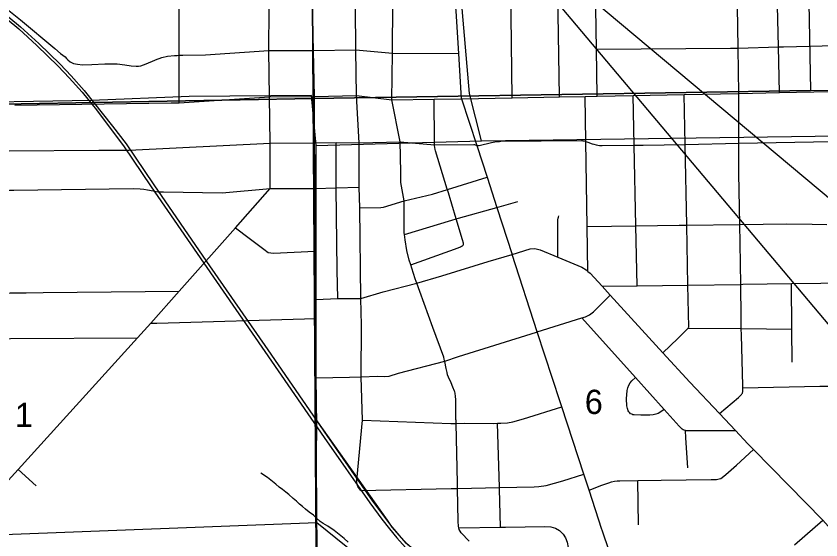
# Model space of a CAD drawing. Extents: x 0 to 34, y 0 to 22.
# Drawn here: x 5.027 to 6.418, y 16.498 to 17.402 of the extents above; entities that cross this region are included whole.
import ezdxf

# ---------------------------------------------------------------- set-up
doc = ezdxf.new("R2010")
doc.units = 0
for name, color, linetype in [('GM_X_City_Street', 7, 'Continuous'), ('GM_X_Corporation', 7, 'Continuous'), ('GM_X_County_Road', 7, 'Continuous'), ('GM_X_Minor_River', 7, 'Continuous'), ('GM_X_Rail_Line', 7, 'Continuous'), ('GM_X_Section', 7, 'Continuous'), ('GM_X_Section_Text', 7, 'Continuous'), ('GM_X_State_Route', 7, 'Continuous'), ('SH_Text', 7, 'Continuous')]:
    doc.layers.add(name, color=color, linetype=linetype)

msp = doc.modelspace()

# ---------------------------------------------------------------- linework, layer by layer
at = {"layer": 'GM_X_City_Street'}
for p, q in [((6.1837, 16.6865), (6.2703, 16.6865)), ((5.03, 16.6191), (5.0615, 16.5908)), ((6.1024, 16.5238), (6.1014, 16.6003))]:
    msp.add_line(p, q, dxfattribs=at)
for points in [[(4.1481, 17.9446), (4.2247, 17.9013), (4.4561, 17.768), (4.7359, 17.6069), (4.8227, 17.5546), (4.8729, 17.5196), (4.9113, 17.4921), (4.9734, 17.4451), (5.0344, 17.3959), (5.0935, 17.3462), (5.1031, 17.338), (5.1112, 17.3317), (5.1139, 17.329), (5.1162, 17.3268)], [(5.4635, 17.3427), (5.4638, 17.4154), (5.4533, 17.4767), (5.4528, 17.5426), (5.4528, 17.5447), (5.4522, 17.6127), (5.4525, 17.6801), (5.4525, 17.6808), (5.4527, 17.749), (5.4527, 17.75), (5.453, 17.829)], [(5.8843, 17.2611), (5.8824, 17.4022), (5.8823, 17.4136), (5.8823, 17.4168), (5.8817, 17.4843), (5.8813, 17.5375), (5.8813, 17.5391), (5.8814, 17.5404), (5.8817, 17.5417), (5.882, 17.5428), (5.8834, 17.5477), (5.8839, 17.5493), (5.8842, 17.5505), (5.8844, 17.5516), (5.8845, 17.5528), (5.8844, 17.5573), (5.8839, 17.6149), (5.8835, 17.6496)], [(6.031, 17.264), (6.0297, 17.3452), (6.0286, 17.416), (6.0286, 17.4204), (6.0275, 17.4867), (6.0266, 17.5475), (6.0265, 17.5507), (6.0255, 17.616)], [(5.9658, 17.2627), (5.9636, 17.4064), (5.9635, 17.4149), (5.9625, 17.4857), (5.9615, 17.5501)], [(5.6139, 17.3439), (5.6132, 17.4171), (5.6124, 17.4855)], [(5.677, 17.3382), (5.6772, 17.3549), (5.6778, 17.4096), (5.6787, 17.481)], [(6.3464, 17.2701), (6.3446, 17.3491), (6.343, 17.4203), (6.343, 17.4229), (6.3428, 17.4295)], [(6.0297, 17.3452), (6.2615, 17.3468), (6.2747, 17.3471), (6.3446, 17.3491), (6.3533, 17.3493), (6.4424, 17.3518), (6.5072, 17.3531), (6.5172, 17.3533), (6.5466, 17.3531), (6.5887, 17.3529), (6.757, 17.352)], [(5.1162, 17.3268), (5.12, 17.3234), (5.1226, 17.322), (5.1256, 17.3207), (5.1294, 17.3197), (5.1329, 17.3191), (5.1414, 17.3184), (5.1573, 17.3187), (5.1801, 17.3198), (5.1922, 17.32), (5.1971, 17.32), (5.1994, 17.3199), (5.2013, 17.3197), (5.2146, 17.318), (5.2257, 17.3163), (5.234, 17.3156), (5.2381, 17.3158), (5.242, 17.3165), (5.247, 17.318), (5.2514, 17.3197), (5.2665, 17.3264), (5.2674, 17.3267), (5.2786, 17.3307), (5.2884, 17.3332), (5.3003, 17.3344), (5.3051, 17.3345), (5.3085, 17.3346), (5.3146, 17.3347), (5.3541, 17.3353), (5.4635, 17.3427)], [(6.1446, 16.8207), (6.1705, 16.8454), (6.1862, 16.8612), (6.1886, 16.8636), (6.1892, 16.8643), (6.1896, 16.865), (6.1881, 16.9377), (6.186, 17.0415), (6.1832, 17.1808), (6.1814, 17.2669)], [(5.8, 17.008), (5.8001, 17.0094), (5.8001, 17.0101), (5.7984, 17.016), (5.7874, 17.052), (5.7721, 17.1026), (5.7718, 17.1033), (5.7517, 17.1698), (5.7511, 17.1717), (5.7503, 17.1756), (5.75, 17.1787), (5.7499, 17.18), (5.7498, 17.1857), (5.7491, 17.2588)], [(6.0151, 16.9614), (6.0139, 17.039), (6.0115, 17.1859), (6.0103, 17.2636)], [(6.1002, 16.9365), (6.098, 17.0402), (6.0949, 17.1793), (6.0931, 17.2652)], [(5.583, 16.9143), (5.5814, 16.9637), (5.5799, 17.1056), (5.5799, 17.1839)], [(5.6226, 16.5831), (5.6187, 16.5879), (5.6175, 16.5898), (5.6167, 16.5916), (5.6161, 16.5939), (5.6158, 16.5958), (5.6155, 16.6), (5.6255, 16.7047), (5.623, 16.7795), (5.6235, 16.8684), (5.6227, 16.9143), (5.6207, 17.0714), (5.6197, 17.1071), (5.6194, 17.1836)], [(5.81, 16.4955), (5.7962, 16.5101), (5.7941, 16.513), (5.7927, 16.5156), (5.7917, 16.5184), (5.7912, 16.5209), (5.7906, 16.5298), (5.7898, 16.5867), (5.7898, 16.5887), (5.7897, 16.5954), (5.7872, 16.6988), (5.7871, 16.7042), (5.787, 16.7052), (5.7866, 16.7382), (5.7861, 16.7473), (5.7859, 16.7495), (5.7856, 16.7513), (5.7852, 16.7531), (5.7847, 16.7546), (5.7817, 16.7617), (5.7786, 16.7688), (5.7739, 16.779), (5.7725, 16.783), (5.7715, 16.7866), (5.7703, 16.7938), (5.7678, 16.8055), (5.7676, 16.8065), (5.7674, 16.8073), (5.7668, 16.81), (5.7658, 16.8134), (5.7469, 16.8644), (5.7245, 16.9267), (5.7194, 16.9409), (5.7182, 16.9441), (5.7166, 16.9487), (5.7106, 16.9672), (5.7088, 16.973), (5.7063, 16.9808), (5.7023, 16.9974), (5.699, 17.016), (5.6978, 17.0251), (5.6974, 17.0278), (5.6975, 17.0833), (5.6914, 17.1152), (5.6917, 17.1309), (5.6911, 17.1603), (5.6906, 17.1854)], [(5.6207, 17.0714), (5.6572, 17.0719), (5.6615, 17.0726), (5.6975, 17.0833), (5.7465, 17.0945), (5.7721, 17.1026), (5.8407, 17.124)], [(4.7895, 17.1005), (4.8605, 17.1009), (4.8969, 17.101), (4.9452, 17.1013), (5.015, 17.1017), (5.0228, 17.1017), (5.2292, 17.1044), (5.2413, 17.1041), (5.2473, 17.1036), (5.2535, 17.1025), (5.2638, 17.1004), (5.2689, 17.0992), (5.2722, 17.0988), (5.2813, 17.0986), (5.3826, 17.0972), (5.4656, 17.1045), (5.5437, 17.1048)], [(5.5437, 17.1048), (5.5799, 17.1056), (5.6197, 17.1071)], [(5.6978, 17.0251), (5.7801, 17.0499), (5.7874, 17.052), (5.7913, 17.0531), (5.8577, 17.072), (5.8942, 17.0823)], [(5.9629, 16.9862), (5.9633, 17.0504), (5.9635, 17.0532), (5.964, 17.0553), (5.9651, 17.0572)], [(6.0139, 17.039), (6.098, 17.0402), (6.1728, 17.0414), (6.186, 17.0415), (6.2778, 17.0424), (6.318, 17.0428), (6.3582, 17.0434), (6.4026, 17.0429), (6.428, 17.0422)], [(5.4056, 17.0366), (5.4297, 17.0187), (5.455, 16.9999), (5.4624, 16.9943), (5.4717, 16.9928), (5.5432, 16.9961)], [(5.7088, 16.973), (5.7906, 17.0022), (5.7947, 17.0039), (5.7965, 17.0048), (5.7982, 17.0057), (5.7989, 17.0062), (5.7994, 17.0067), (5.8, 17.008)], [(6.0395, 16.9356), (6.1002, 16.9365), (6.1881, 16.9377), (6.2793, 16.939), (6.2831, 16.9391), (6.3668, 16.9403), (6.4176, 16.941), (6.4415, 16.9414), (6.5008, 16.9424), (6.5679, 16.9435), (6.6341, 16.9446), (6.6397, 16.9447), (6.7024, 16.9457), (6.7059, 16.9458), (6.7144, 16.9459)], [(6.3679, 16.8047), (6.3675, 16.8616), (6.3668, 16.9403)], [(4.7893, 16.9222), (4.9006, 16.9233), (4.9484, 16.9237), (5.0165, 16.9244), (5.0439, 16.9246), (5.0733, 16.9249), (5.3084, 16.9272)], [(5.5455, 16.7774), (5.603, 16.7785), (5.623, 16.7795), (5.6516, 16.7802), (5.6635, 16.78), (5.6714, 16.7805), (5.6876, 16.7856), (5.7676, 16.8065), (5.7916, 16.8142), (5.9262, 16.8566), (5.9276, 16.857), (6.0043, 16.8812), (6.0107, 16.8832), (6.0178, 16.8864), (6.0246, 16.8914), (6.0535, 16.9203)], [(6.1876, 16.6223), (6.1844, 16.674), (6.1837, 16.6865), (6.1817, 16.687), (6.1798, 16.6879), (6.1783, 16.6889), (6.1768, 16.6902), (6.1726, 16.6943), (6.1469, 16.7227), (6.0971, 16.7781), (6.0043, 16.8812)], [(6.1886, 16.8636), (6.2803, 16.8626), (6.3675, 16.8616)], [(4.7906, 16.8438), (4.8854, 16.8445), (4.9028, 16.8446), (4.9453, 16.8449), (5.0171, 16.8453), (5.2367, 16.8468)], [(6.1469, 16.7227), (6.1397, 16.7177), (6.1366, 16.7159), (6.1325, 16.7146), (6.1279, 16.7137), (6.1219, 16.7133), (6.1067, 16.713), (6.0949, 16.7136), (6.0929, 16.7139), (6.0909, 16.7146), (6.0889, 16.7156), (6.0873, 16.7169), (6.0859, 16.7188), (6.0848, 16.7206), (6.0834, 16.7245), (6.0826, 16.729), (6.082, 16.7411), (6.083, 16.7556), (6.084, 16.7601), (6.0859, 16.7647), (6.0884, 16.7689), (6.0912, 16.7722), (6.0971, 16.7781)], [(6.2829, 16.7601), (6.4163, 16.7629), (6.4349, 16.7632), (6.447, 16.7626), (6.4675, 16.7618), (6.4865, 16.7613), (6.5013, 16.7611), (6.5054, 16.7612), (6.5164, 16.7614), (6.5707, 16.7623), (6.6393, 16.7636), (6.7072, 16.7648), (6.7836, 16.7662)], [(5.6255, 16.7047), (5.7784, 16.6986), (5.7872, 16.6988), (5.8015, 16.6993), (5.8524, 16.6989), (5.8588, 16.699), (5.8644, 16.699), (5.8759, 16.6997), (5.8853, 16.7013), (5.9035, 16.7065), (5.9699, 16.7272)], [(5.8639, 16.5197), (5.862, 16.5857), (5.862, 16.588), (5.8588, 16.699)], [(6.0172, 16.5835), (6.0389, 16.592), (6.0511, 16.5963), (6.0559, 16.5979), (6.0611, 16.599), (6.0656, 16.5996), (6.07, 16.5999), (6.1014, 16.6003), (6.142, 16.6008), (6.2281, 16.6021), (6.2372, 16.6022), (6.2398, 16.6025), (6.2422, 16.603), (6.2447, 16.6039), (6.247, 16.6054), (6.2534, 16.6104), (6.2721, 16.627), (6.3014, 16.6537)], [(5.6226, 16.5831), (5.7788, 16.5865), (5.7898, 16.5867), (5.862, 16.588), (5.9221, 16.5891), (5.9301, 16.5896), (5.943, 16.5917), (5.9717, 16.5997), (6.0081, 16.6112)], [(5.7917, 16.5184), (5.8639, 16.5197), (5.8724, 16.5198), (5.9409, 16.521), (5.9508, 16.5204), (5.9592, 16.5181), (5.966, 16.5138), (5.9722, 16.5078), (5.9765, 16.501), (5.9791, 16.4935), (5.9808, 16.4848), (5.9817, 16.4746), (5.9826, 16.4625)]]:
    msp.add_lwpolyline(points, dxfattribs=at)
at = {"layer": 'GM_X_Corporation'}
msp.add_lwpolyline([(5.6299, 16.46), (5.5464, 16.5271), (4.7945, 16.4985)], dxfattribs=at)
at = {"layer": 'GM_X_County_Road'}
for p, q in [((5.6149, 17.2651), (5.6139, 17.3439)), ((5.6194, 17.1836), (5.6149, 17.2651))]:
    msp.add_line(p, q, dxfattribs=at)
for points in [[(5.5425, 17.2636), (5.5405, 17.3429), (5.5388, 17.4169), (5.5378, 17.4844), (5.5371, 17.5514), (5.5372, 17.6185), (5.5367, 17.6863), (5.5364, 17.7569), (5.5358, 17.8344), (5.5351, 17.9031), (5.5346, 18.0161)], [(5.3087, 17.2528), (5.3085, 17.3346), (5.3084, 17.3966), (5.3084, 17.4042), (5.3083, 17.4734), (5.3083, 17.5427), (5.3083, 17.5764), (5.3082, 17.6037), (5.308, 17.6793), (5.3079, 17.6981), (5.3074, 17.7045), (5.3066, 17.7102), (5.3046, 17.7183), (5.3031, 17.722), (5.3018, 17.7246), (5.2893, 17.7472), (5.2454, 17.8264), (5.2187, 17.8971)], [(6.28, 16.8817), (6.2793, 16.939), (6.2783, 17.0104), (6.2778, 17.0424), (6.2761, 17.1306), (6.2761, 17.1826), (6.2762, 17.2688), (6.2747, 17.3471), (6.2734, 17.4188)], [(5.4635, 17.3427), (5.5405, 17.3429), (5.6139, 17.3439), (5.677, 17.3382), (5.7921, 17.3377)], [(5.4656, 17.1045), (5.4656, 17.1826), (5.4645, 17.263), (5.4635, 17.3427)], [(5.6906, 17.1854), (5.676, 17.2579), (5.677, 17.3382)], [(6.0115, 17.1859), (6.0149, 17.1848), (6.0225, 17.1818), (6.0255, 17.1809), (6.0291, 17.18), (6.0321, 17.1794), (6.035, 17.179), (6.04, 17.1787), (6.0949, 17.1793), (6.1107, 17.1795), (6.1832, 17.1808), (6.2761, 17.1826), (6.4375, 17.1855), (6.4899, 17.1865), (6.4982, 17.1866), (6.5584, 17.188), (6.5663, 17.1881), (6.626, 17.1893), (6.8006, 17.1927), (6.828, 17.1935), (6.8565, 17.1955), (6.9136, 17.2006)], [(5.0067, 17.1695), (5.0144, 17.1695), (5.1695, 17.1705), (5.1907, 17.1709), (5.2221, 17.171), (5.4656, 17.1826), (5.5424, 17.1836)], [(5.5424, 17.1836), (5.5799, 17.1839), (5.6194, 17.1836), (5.6906, 17.1854), (5.7499, 17.18), (5.8177, 17.1808), (5.8192, 17.1805), (5.8203, 17.1802), (5.8228, 17.179), (5.8238, 17.1789), (5.825, 17.1789), (5.8261, 17.179), (5.827, 17.1791), (5.8484, 17.1839), (5.8544, 17.1852), (5.8568, 17.1855), (5.8591, 17.1858), (5.862, 17.186), (5.8646, 17.1861), (6.004, 17.1872), (6.005, 17.1872), (6.0064, 17.1871), (6.0076, 17.187), (6.0089, 17.1867), (6.0101, 17.1863), (6.0115, 17.1859)], [(5.2594, 16.8718), (5.3084, 16.9272), (5.4056, 17.0366), (5.4656, 17.1045)], [(5.6227, 16.9143), (5.6613, 16.9259), (5.7194, 16.9409), (5.7625, 16.9538), (5.8428, 16.9787), (5.8842, 16.9903)], [(6.0398, 16.5147), (6.0394, 16.5157), (6.0172, 16.5835), (6.0081, 16.6112), (5.9699, 16.7272), (5.9669, 16.7364), (5.9276, 16.857), (5.8842, 16.9903)], [(5.5447, 16.913), (5.583, 16.9143), (5.6227, 16.9143)], [(5.5466, 16.5236), (5.5465, 16.5347), (5.5457, 16.6416), (5.5467, 16.6961), (5.5455, 16.7774), (5.5447, 16.8801)], [(6.2427, 16.7159), (6.2752, 16.7437), (6.2805, 16.7488), (6.2814, 16.7499), (6.2821, 16.7511), (6.2825, 16.7521), (6.2827, 16.7531), (6.2829, 16.7554), (6.283, 16.7579), (6.2829, 16.7601), (6.2828, 16.7645), (6.2804, 16.8512), (6.2803, 16.8626), (6.28, 16.8817)], [(6.3722, 16.4893), (6.3902, 16.5044), (6.4212, 16.5319)], [(5.552, 15.8685), (5.5516, 15.9077), (5.5507, 16.0068), (5.5494, 16.1864), (5.5493, 16.3182), (5.5486, 16.379), (5.5477, 16.4263), (5.5467, 16.4698), (5.547, 16.4932), (5.5468, 16.5074), (5.5466, 16.5236)], [(6.1317, 16.258), (6.1173, 16.2956), (6.0982, 16.3453), (6.0941, 16.3559), (6.0617, 16.4482), (6.056, 16.4656), (6.0522, 16.4769), (6.0398, 16.5147)]]:
    msp.add_lwpolyline(points, dxfattribs=at)
at = {"layer": 'GM_X_Minor_River'}
for points in [[(5.5115, 16.5646), (5.5054, 16.5694), (5.498, 16.5761), (5.493, 16.5802), (5.4873, 16.5846), (5.4811, 16.589), (5.4757, 16.5939), (5.4672, 16.6009), (5.4611, 16.6053), (5.4499, 16.6127)], [(5.6005, 16.4939), (5.5939, 16.5002), (5.5851, 16.5069), (5.5766, 16.5139), (5.5655, 16.5213), (5.5574, 16.5257), (5.552, 16.5297), (5.5451, 16.5357), (5.5408, 16.5405), (5.5335, 16.5457), (5.527, 16.5505), (5.5216, 16.5553), (5.5166, 16.5594), (5.5115, 16.5646)]]:
    msp.add_lwpolyline(points, dxfattribs=at)
at = {"layer": 'GM_X_Rail_Line'}
msp.add_line((5.5454, 17.1789), (5.8309, 17.1868), dxfattribs=at)
for points in [[(5.8309, 17.1868), (5.8105, 17.2685), (5.7839, 17.5759), (6.0398, 17.9469)], [(5.0113, 17.3969), (5.0313, 17.3802), (5.0627, 17.3515), (5.0994, 17.316), (5.1183, 17.2959), (5.1409, 17.271), (5.1658, 17.2404), (5.189, 17.209), (5.2125, 17.1783), (5.26, 17.1076), (5.3514, 16.9755), (5.4568, 16.823), (5.5592, 16.6747), (5.6383, 16.5614), (5.6587, 16.5333), (5.6719, 16.5165), (5.6849, 16.5011), (5.7, 16.4845)], [(5.0143, 17.4005), (5.0344, 17.3838), (5.0659, 17.3549), (5.1028, 17.3193), (5.1217, 17.2991), (5.1444, 17.2741), (5.1935, 17.2123), (5.2171, 17.1816), (5.2647, 17.1108), (5.356, 16.9787), (5.4615, 16.8262), (5.5639, 16.6779), (5.6429, 16.5646), (5.6632, 16.5367), (5.6763, 16.5201), (5.6892, 16.5048), (5.7041, 16.4883)], [(5.1569, 17.2563), (4.8882, 17.2522), (4.6131, 17.2468), (3.47, 17.2222), (2.5105, 17.2141), (2.1, 17.2106)], [(5.5454, 17.1789), (5.5374, 17.2651), (5.3256, 17.2634), (5.1569, 17.2563)], [(5.8309, 17.1868), (6.4495, 17.1956), (6.9135, 17.2015)], [(6.4589, 15.838), (6.3957, 15.9535), (6.3777, 15.9883), (6.3611, 16.0179), (6.3479, 16.0484), (6.3213, 16.0864), (6.3001, 16.1053), (6.2789, 16.1241), (6.2331, 16.1554), (6.174, 16.189), (6.1473, 16.2058), (5.8856, 16.3705), (5.8449, 16.3961), (5.8359, 16.4018), (5.8018, 16.4237), (5.7435, 16.4591), (5.7326, 16.4666), (5.7217, 16.474), (5.7012, 16.4915), (5.6767, 16.5199), (5.6686, 16.5315), (5.5455, 16.7057), (5.5454, 17.1789)]]:
    msp.add_lwpolyline(points, dxfattribs=at)
at = {"layer": 'GM_X_Section'}
for points in [[(5.5332, 18.2617), (6.3807, 18.2734), (6.4001, 17.2736), (5.5401, 17.2602)], [(4.5147, 18.2545), (5.5332, 18.2617), (5.5401, 17.2602), (4.5299, 17.2417)], [(6.4001, 17.2736), (6.5093, 17.2749), (6.5053, 16.2508), (5.5468, 16.2132), (5.5401, 17.2602)], [(5.5401, 17.2602), (5.5468, 16.2132), (4.5462, 16.1923), (4.5299, 17.2417)]]:
    msp.add_lwpolyline(points, close=True, dxfattribs=at)
at = {"layer": 'GM_X_State_Route'}
for p, q in [((5.7966, 17.2594), (5.7921, 17.3377)), ((5.3087, 17.2528), (5.4645, 17.263)), ((5.4645, 17.263), (5.5425, 17.2636)), ((5.5425, 17.2636), (5.6149, 17.2651)), ((5.6149, 17.2651), (5.676, 17.2579)), ((5.676, 17.2579), (5.7491, 17.2588)), ((5.7491, 17.2588), (5.7966, 17.2594)), ((5.5447, 16.902), (5.5447, 16.913)), ((5.2594, 16.8718), (5.27, 16.8721))]:
    msp.add_line(p, q, dxfattribs=at)
for points in [[(5.7921, 17.3377), (5.7873, 17.4109), (5.7812, 17.4827), (5.7752, 17.5482), (5.7741, 17.5612), (5.7743, 17.5673), (5.7754, 17.5715), (5.7772, 17.5761), (5.8041, 17.6143), (5.827, 17.647), (5.9723, 17.8517), (5.9838, 17.8679)], [(5.7966, 17.2594), (5.8843, 17.2611), (5.9658, 17.2627), (6.0103, 17.2636), (6.031, 17.264), (6.0931, 17.2652), (6.1814, 17.2669), (6.2762, 17.2688), (6.3464, 17.2701), (6.4348, 17.2719), (6.4985, 17.2731), (6.5079, 17.2733), (6.5641, 17.2744), (6.7387, 17.2778), (6.7751, 17.2785)], [(5.0242, 17.2487), (5.2944, 17.2526), (5.3087, 17.2528)], [(5.5447, 16.913), (5.5432, 16.9961), (5.5437, 17.1048), (5.5424, 17.1836), (5.5425, 17.2636)], [(5.7966, 17.2594), (5.8228, 17.179), (5.8407, 17.124), (5.8577, 17.072), (5.8842, 16.9903)], [(5.8842, 16.9903), (5.9153, 17.0001), (5.9232, 17.001), (5.9324, 16.9989), (5.9629, 16.9862), (6.0047, 16.9689), (6.0119, 16.9641), (6.0151, 16.9614), (6.0189, 16.9581), (6.0395, 16.9356), (6.0535, 16.9203), (6.1446, 16.8207), (6.191, 16.77), (6.2427, 16.7159), (6.2703, 16.6865), (6.2915, 16.6638), (6.3014, 16.6537), (6.3618, 16.592), (6.4212, 16.5319), (6.4722, 16.4742), (6.4755, 16.4704)], [(5.27, 16.8721), (5.5447, 16.8801), (5.5447, 16.902)], [(4.9238, 16.5022), (4.9586, 16.5406), (5.0018, 16.5881), (5.03, 16.6191), (5.2367, 16.8468), (5.2594, 16.8718)]]:
    msp.add_lwpolyline(points, dxfattribs=at)
at = {"layer": 'SH_Text'}
msp.add_lwpolyline([(5.8041, 17.6143), (7.0506, 16.5706), (7.0506, 16.1356)], close=True, dxfattribs=at)

# ---------------------------------------------------------------- texts
at = {"layer": 'GM_X_Section_Text'}
for s, p in [('6', (6.0097, 16.7151)), ('1', (5.0247, 16.6926))]:
    msp.add_text(s, height=0.0419, rotation=0, dxfattribs=at).set_placement(p)

doc.saveas('drawing.dxf')
